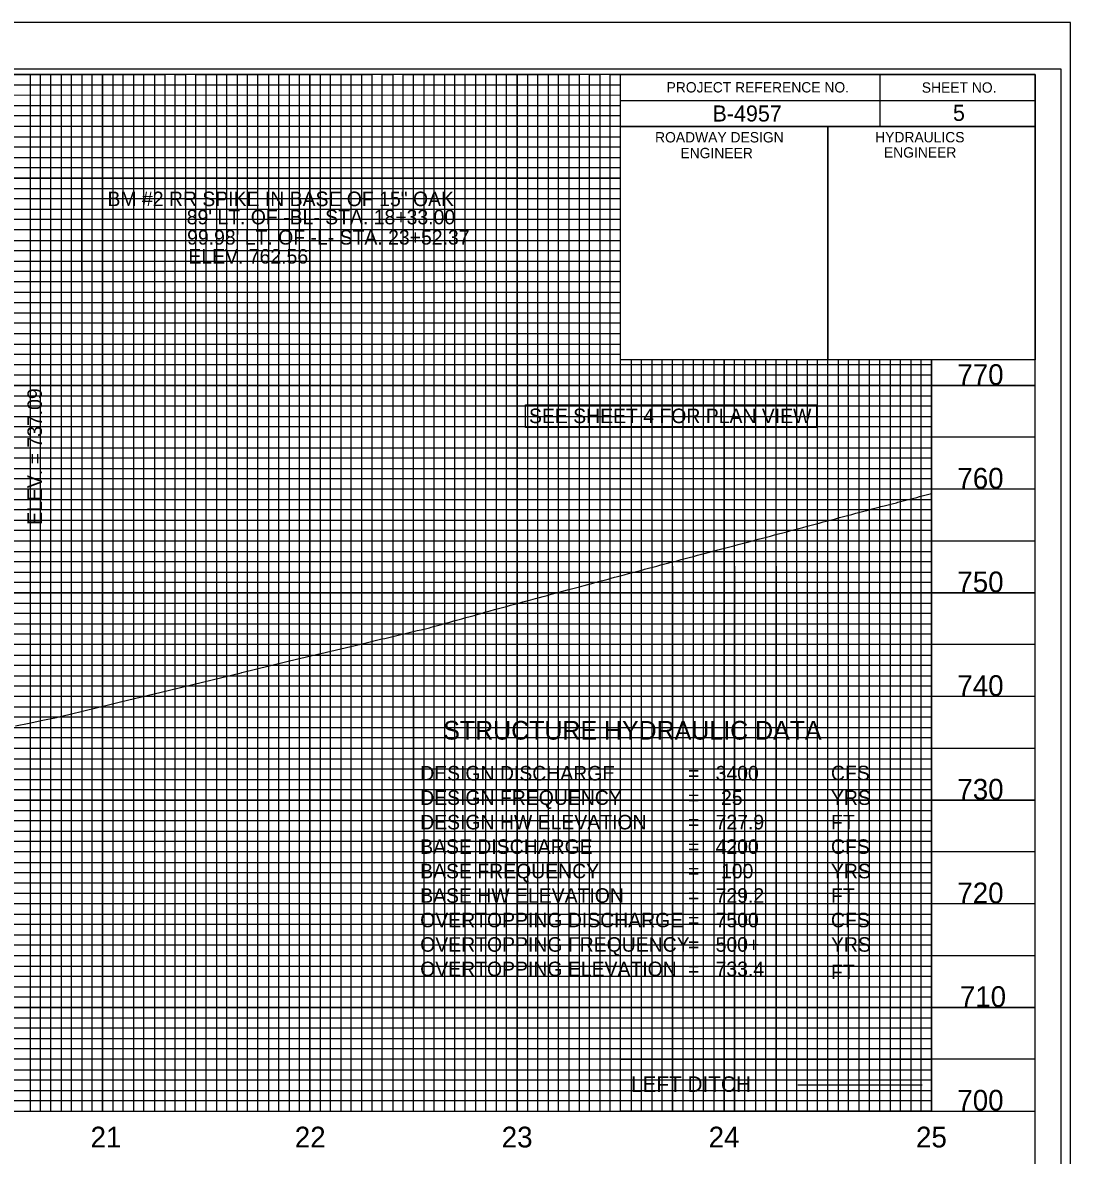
# Model space of a CAD drawing. Extents: x 573926 to 575610, y -51565 to -50465.
# Drawn here: x 575104 to 575610, y -51011 to -50465 of the extents above; entities that cross this region are included whole.
import ezdxf

# ---------------------------------------------------------------- set-up
doc = ezdxf.new("R2010")
doc.units = 0
for name, color, linetype in [('Exist Vertical Profile Ground Line', 7, 'Continuous'), ('Exist Vertical Profile Horizontal Axis Label Major', 7, 'Continuous'), ('Exist Vertical Profile Vertical Axis Label', 7, 'Continuous'), ('Prop Dimension Text', 7, 'Continuous'), ('Prop Grid Mask', 7, 'Continuous'), ('Prop PFL Ditch Label CELL', 7, 'Continuous'), ('Prop PFL Structure Hydraulic Data Label CELL', 7, 'Continuous'), ('Prop PFL Text', 7, 'Continuous'), ('Sheet Cutting Line CELL', 7, 'Continuous'), ('Sheet Data Field CELL', 7, 'Continuous'), ('Sheet DOT Grid CELL', 7, 'Continuous'), ('Sheet Layout Profile Border Port 1', 7, 'Continuous'), ('Sheet Plot Border Inside CELL', 7, 'Continuous'), ('Sheet Plot Border Outside CELL', 7, 'Continuous'), ('Sheet Profile CELL', 7, 'Continuous'), ('Sheet Profile Grid Major CELL', 7, 'Continuous'), ('Sheet Profile Grid Middle CELL', 7, 'Continuous'), ('Sheet Profile Grid Minor CELL', 7, 'Continuous')]:
    doc.layers.add(name, color=color, linetype=linetype)

msp = doc.modelspace()

# ---------------------------------------------------------------- linework, layer by layer
at = {"layer": 'Exist Vertical Profile Ground Line'}
for points in [[(575382.79, -50734.35), (575384.75, -50733.83), (575386.71, -50733.3), (575388.67, -50732.78), (575389.37, -50732.59), (575389.89, -50732.46), (575390.63, -50732.26), (575392.59, -50731.74), (575394.55, -50731.21), (575396.5, -50730.69), (575398.46, -50730.17), (575400.42, -50729.65), (575402.38, -50729.13), (575404.03, -50728.7), (575404.34, -50728.61), (575406.3, -50728.09), (575408.26, -50727.57), (575410.22, -50727.05), (575412.18, -50726.53), (575414.14, -50726.02), (575416.1, -50725.5), (575417.17, -50725.22), (575417.48, -50725.14), (575418.06, -50724.99), (575420.02, -50724.47), (575421.98, -50723.94), (575423.94, -50723.42), (575425.9, -50722.9), (575427.86, -50722.38), (575429.81, -50721.86), (575431.77, -50721.34), (575433.73, -50720.83), (575435.69, -50720.31), (575437.2, -50719.91), (575437.65, -50719.8), (575439.61, -50719.28), (575441.57, -50718.76), (575443.53, -50718.24), (575445.49, -50717.72), (575447.45, -50717.21), (575449.41, -50716.69), (575451.37, -50716.17), (575453.33, -50715.65), (575455.29, -50715.14), (575457.53, -50714.55), (575458.04, -50714.42), (575459.21, -50714.11), (575461.17, -50713.59), (575463.12, -50713.08), (575465.08, -50712.56), (575467.04, -50712.04), (575469, -50711.52), (575470.96, -50711), (575471.63, -50710.82), (575472.92, -50710.48), (575474.88, -50709.96), (575476.84, -50709.43), (575478.8, -50708.91), (575480.76, -50708.39), (575482.72, -50707.86), (575484.68, -50707.34), (575486.64, -50706.82), (575488.6, -50706.29), (575490.56, -50705.77), (575491.89, -50705.42), (575492.52, -50705.25), (575494.48, -50704.73), (575496.43, -50704.2), (575498.39, -50703.68), (575500.35, -50703.16), (575502.31, -50702.63), (575504.27, -50702.11), (575506.23, -50701.59), (575508.19, -50701.07), (575510.15, -50700.54), (575512.15, -50700.01), (575514.07, -50699.51), (575516.03, -50698.99), (575517.99, -50698.48), (575518.37, -50698.38), (575519.95, -50697.97), (575521.91, -50697.47), (575523.87, -50696.97), (575525.83, -50696.47), (575526.5, -50696.3), (575527.79, -50695.96), (575529.74, -50695.45), (575531.7, -50694.94), (575533.66, -50694.43), (575535.62, -50693.92), (575537.01, -50693.57), (575537.58, -50693.41), (575539.54, -50692.87), (575541.5, -50692.33), (575542.78, -50691.98)], [(575100.76, -50804.12), (575107.36, -50802.75), (575113.97, -50801.38), (575120.57, -50800.01), (575121.06, -50799.91), (575127.18, -50798.43), (575133.78, -50796.84), (575140.39, -50795.25), (575146.99, -50793.66), (575151.41, -50792.6), (575174.39, -50787.01), (575181.62, -50785.26), (575209.6, -50778.47), (575210.05, -50778.35), (575237.62, -50771.66), (575238.53, -50771.43), (575267.42, -50764.65), (575269.96, -50764.02), (575276.98, -50762.37), (575278.94, -50761.91), (575280.9, -50761.45), (575282.86, -50760.98), (575284.82, -50760.52), (575286.78, -50760.06), (575288.74, -50759.59), (575290.7, -50759.13), (575292.66, -50758.67), (575294.61, -50758.2), (575296.57, -50757.74), (575297.22, -50757.58), (575297.79, -50757.43), (575298.69, -50757.33), (575300.49, -50756.85), (575301.43, -50756.59), (575302.45, -50756.27), (575303.15, -50756.05), (575304.41, -50755.7), (575306.37, -50755.16), (575308.33, -50754.62), (575310.29, -50754.08), (575312.25, -50753.54), (575314.21, -50753), (575316.17, -50752.46), (575318.13, -50751.92), (575320.09, -50751.38), (575322.05, -50750.84), (575324.01, -50750.3), (575325.37, -50749.93), (575325.97, -50749.75), (575327.3, -50749.35), (575327.92, -50749.16), (575329.2, -50748.79), (575329.88, -50748.61), (575331.84, -50748.07), (575333.8, -50747.54), (575335.76, -50747.01), (575337.72, -50746.47), (575339.68, -50745.94), (575341.64, -50745.41), (575343.6, -50744.89), (575345.56, -50744.36), (575347.52, -50743.83), (575349.48, -50743.31), (575351.7, -50742.71), (575353.62, -50742.19), (575355.36, -50741.73), (575357.32, -50741.2), (575359.28, -50740.67), (575361.23, -50740.15), (575363.19, -50739.62), (575365.38, -50739.04), (575367.11, -50738.57), (575369.07, -50738.04), (575371.03, -50737.51), (575372.99, -50736.99), (575375.18, -50736.4), (575376.91, -50735.94), (575378.87, -50735.41), (575380.83, -50734.88), (575382.79, -50734.35)]]:
    msp.add_lwpolyline(points, dxfattribs=at)
at = {"layer": 'Prop Grid Mask'}
for points in [[(575132.78, -50539.95), (575342.78, -50539.95), (575342.78, -50584.95), (575132.78, -50584.95)], [(575346.87, -50649.35), (575487.28, -50649.35), (575487.28, -50660.17), (575346.87, -50660.17)], [(575292.78, -50939.95), (575517.78, -50939.95), (575517.78, -50789.95), (575292.78, -50789.95)], [(575392.78, -50964.95), (575542.78, -50964.95), (575542.78, -50989.95), (575392.78, -50989.95)]]:
    msp.add_lwpolyline(points, close=True, dxfattribs=at)
at = {"layer": 'Prop PFL Ditch Label CELL'}
msp.add_line((575478.33, -50977.25), (575538.33, -50977.25), dxfattribs=at)
at = {"layer": 'Sheet Cutting Line CELL'}
msp.add_line((575609.78, -50464.95), (573925.78, -50464.95), dxfattribs=at)
at = {"layer": 'Sheet DOT Grid CELL'}
for p, q in [((575142.78, -50989.95), (575142.78, -50489.95)), ((575192.78, -50989.95), (575192.78, -50489.95)), ((575242.78, -50989.95), (575242.78, -50489.95)), ((575292.78, -50989.95), (575292.78, -50489.95)), ((575342.78, -50989.95), (575342.78, -50489.95)), ((575392.73, -50539.95), (574092.78, -50539.95)), ((575392.73, -50589.95), (574092.78, -50589.95)), ((575392.78, -50989.95), (575392.78, -50627.5)), ((575442.78, -50989.95), (575442.78, -50627.5)), ((575492.78, -50989.95), (575492.78, -50627.5)), ((575542.78, -50989.95), (575542.78, -50627.5)), ((575592.78, -50639.95), (574092.78, -50639.95)), ((575592.78, -50689.95), (574092.78, -50689.95)), ((575592.78, -50739.95), (574092.78, -50739.95)), ((575592.78, -50789.95), (574092.78, -50789.95)), ((575592.78, -50839.95), (574092.78, -50839.95)), ((575592.78, -50889.95), (574092.78, -50889.95)), ((575592.78, -50939.95), (574092.78, -50939.95))]:
    msp.add_line(p, q, dxfattribs=at)
at = {"layer": 'Sheet Layout Profile Border Port 1'}
msp.add_lwpolyline([(574142.78, -50489.95), (574142.78, -50989.95), (575542.78, -50989.95), (575542.78, -50627.5), (575392.73, -50627.5), (575392.73, -50489.95)], close=True, dxfattribs=at)
at = {"layer": 'Sheet Plot Border Inside CELL'}
msp.add_lwpolyline([(573938.78, -51542.5), (575605.28, -51542.5), (575605.28, -50487.4), (573938.78, -50487.4)], close=True, dxfattribs=at)
at = {"layer": 'Sheet Plot Border Outside CELL'}
msp.add_lwpolyline([(573925.78, -51564.95), (575609.78, -51564.95), (575609.78, -50464.95), (573925.78, -50464.95)], close=True, dxfattribs=at)
at = {"layer": 'Sheet Profile CELL'}
for p, q in [((575517.78, -50490), (575517.78, -50515)), ((575392.73, -50502.5), (575592.78, -50502.5)), ((575492.78, -50515), (575492.78, -50627.45)), ((574092.78, -50989.95), (575592.78, -50989.95))]:
    msp.add_line(p, q, dxfattribs=at)
for points in [[(575592.78, -50489.95), (574092.78, -50489.95), (574092.78, -51539.95), (575592.78, -51539.95)], [(575392.73, -50489.95), (575592.78, -50489.95), (575592.78, -50515), (575392.73, -50515)], [(575392.73, -50515), (575492.78, -50515), (575492.78, -50627.5), (575392.73, -50627.5)], [(575492.78, -50515), (575592.78, -50515), (575592.78, -50627.5), (575492.78, -50627.5)]]:
    msp.add_lwpolyline(points, close=True, dxfattribs=at)
at = {"layer": 'Sheet Profile Grid Major CELL'}
for points in [[(575092.78, -50489.95), (575142.78, -50489.95), (575142.78, -50989.95), (575192.78, -50989.95), (575192.78, -50489.95), (575242.78, -50489.95), (575242.78, -50989.95), (575292.78, -50989.95), (575292.78, -50489.95), (575342.78, -50489.95), (575342.78, -50989.95), (575392.78, -50989.95), (575392.78, -50489.95), (575419.08, -50489.95)], [(574092.78, -50539.95), (575392.78, -50539.95)], [(575392.78, -50589.95), (574092.78, -50589.95), (574092.78, -50639.95), (575592.78, -50639.95)], [(575442.78, -50627.5), (575442.78, -50989.95), (575492.78, -50989.95), (575492.78, -50989.95), (575492.78, -50627.5)], [(575542.78, -50627.5), (575542.78, -50989.95), (575592.78, -50989.95), (575592.78, -50639.95)], [(575592.78, -50689.95), (574092.78, -50689.95), (574092.78, -50739.95), (575592.78, -50739.95)], [(575592.78, -50789.95), (574092.78, -50789.95), (574092.78, -50839.95), (575592.78, -50839.95)], [(575592.78, -50889.95), (574092.78, -50889.95), (574092.78, -50889.95), (574092.78, -50939.95), (575592.78, -50939.95)]]:
    msp.add_lwpolyline(points, dxfattribs=at)
at = {"layer": 'Sheet Profile Grid Middle CELL'}
msp.add_line((574092.78, -50514.95), (575392.73, -50514.95), dxfattribs=at)
for points in [[(575067.78, -50989.95), (575117.78, -50989.95), (575117.78, -50489.95), (575167.78, -50489.95), (575167.78, -50989.95), (575217.78, -50989.95), (575217.78, -50489.95), (575267.78, -50489.95), (575267.78, -50989.95), (575317.78, -50989.95), (575317.78, -50489.95), (575367.78, -50489.95), (575367.78, -50989.95), (575417.78, -50989.95), (575417.78, -50627.5)], [(575392.78, -50564.95), (574092.78, -50564.95), (574092.78, -50614.95), (575392.78, -50614.95)], [(575417.78, -50727.15), (575417.78, -50989.95), (575467.78, -50989.95), (575467.78, -50627.5)], [(575467.78, -50727.15), (575467.78, -50989.95), (575517.78, -50989.95), (575517.78, -50627.5)], [(575592.78, -50664.95), (574092.78, -50664.95), (574092.78, -50714.95), (575417.78, -50714.95)], [(575417.78, -50714.95), (575592.78, -50714.95)], [(575592.78, -50764.95), (574092.78, -50764.95), (574092.78, -50814.95), (575592.78, -50814.95)], [(575592.78, -50864.95), (574092.78, -50864.95), (574092.78, -50914.95), (575592.78, -50914.95)], [(575592.78, -50964.95), (574092.78, -50964.95)]]:
    msp.add_lwpolyline(points, dxfattribs=at)
at = {"layer": 'Sheet Profile Grid Minor CELL'}
for p, q in [((574142.78, -50494.95), (575392.78, -50494.95)), ((575392.78, -50499.95), (574142.78, -50500.3)), ((574142.78, -50504.95), (575392.78, -50504.95)), ((575392.73, -50624.95), (574142.78, -50624.95)), ((575542.78, -50629.95), (574142.78, -50629.95)), ((575542.78, -50634.95), (574142.78, -50634.95)), ((574142.78, -50644.95), (575542.78, -50644.95)), ((575542.78, -50649.95), (574142.78, -50649.95)), ((574142.78, -50654.95), (575542.78, -50654.95)), ((575542.78, -50674.95), (574142.78, -50674.95)), ((574142.78, -50679.95), (575542.78, -50679.95)), ((575542.78, -50699.95), (574142.78, -50699.95)), ((574142.78, -50704.95), (575542.78, -50704.95)), ((575542.78, -50724.95), (574142.78, -50724.95)), ((574142.78, -50729.95), (575542.78, -50729.95)), ((575542.78, -50734.95), (574142.78, -50734.95)), ((574142.78, -50744.95), (575542.78, -50744.95)), ((575542.78, -50749.95), (574142.78, -50749.95)), ((574142.78, -50754.95), (575542.78, -50754.95)), ((575542.78, -50759.95), (574142.78, -50759.95)), ((574142.78, -50769.95), (575542.78, -50769.95)), ((575542.78, -50774.95), (574142.78, -50774.95)), ((574142.78, -50779.95), (575542.78, -50779.95)), ((575542.78, -50784.95), (574142.78, -50784.95)), ((574142.78, -50794.95), (575542.78, -50794.95)), ((575542.78, -50799.95), (574142.78, -50799.95)), ((574142.78, -50804.95), (575542.78, -50804.95)), ((575542.78, -50809.95), (574142.78, -50809.95)), ((574142.78, -50819.95), (575542.78, -50819.95)), ((575542.78, -50824.95), (574142.78, -50824.95)), ((574142.78, -50829.95), (575542.78, -50829.95)), ((575542.78, -50834.95), (574142.78, -50834.95)), ((574142.78, -50844.95), (575542.78, -50844.95)), ((575542.78, -50849.95), (574142.78, -50849.95)), ((574142.78, -50854.95), (575542.78, -50854.95)), ((575542.78, -50859.95), (574142.78, -50859.95)), ((574142.78, -50869.95), (575542.78, -50869.95)), ((575542.78, -50874.95), (574142.78, -50874.95)), ((575542.78, -50879.95), (574142.78, -50879.95)), ((575542.78, -50884.95), (574142.78, -50884.95)), ((574142.78, -50894.95), (575542.78, -50894.95)), ((575542.78, -50899.95), (574142.78, -50899.95)), ((574142.78, -50904.95), (575542.78, -50904.95)), ((575542.78, -50909.95), (574142.78, -50909.95)), ((574142.78, -50919.95), (575542.78, -50919.95)), ((575542.78, -50924.95), (574142.78, -50924.95)), ((574142.78, -50929.95), (575542.78, -50929.95)), ((575542.78, -50934.95), (574142.78, -50934.95)), ((574142.78, -50944.95), (575542.78, -50944.95)), ((575542.78, -50949.95), (574142.78, -50949.95)), ((574142.78, -50954.95), (575542.78, -50954.95)), ((575542.78, -50959.95), (574142.78, -50959.95)), ((574142.78, -50969.95), (575542.78, -50969.95)), ((575542.78, -50974.95), (574142.78, -50974.95)), ((574142.78, -50979.95), (575542.78, -50979.95))]:
    msp.add_line(p, q, dxfattribs=at)
for points in [[(575102.78, -50489.95), (575107.78, -50489.95), (575107.78, -50989.95), (575112.78, -50989.95), (575112.78, -50489.95), (575122.78, -50489.95), (575122.78, -50989.95), (575127.78, -50989.95), (575127.78, -50489.95), (575132.78, -50489.95), (575132.78, -50989.95), (575137.78, -50989.95), (575137.78, -50489.95), (575147.78, -50489.95), (575147.78, -50989.95), (575152.78, -50989.95), (575152.78, -50489.95), (575157.78, -50489.95), (575157.78, -50989.95), (575162.78, -50989.95), (575162.78, -50489.95), (575172.78, -50489.95), (575172.78, -50989.95), (575177.78, -50989.95), (575177.78, -50489.95), (575182.78, -50489.95), (575182.78, -50989.95), (575187.78, -50989.95), (575187.78, -50489.95), (575197.78, -50489.95), (575197.78, -50989.95), (575202.78, -50989.95), (575202.78, -50489.95), (575207.78, -50489.95), (575207.78, -50989.95), (575212.78, -50989.95), (575212.78, -50489.95), (575222.78, -50489.95), (575222.78, -50989.95), (575227.78, -50989.95), (575227.78, -50489.95), (575232.78, -50489.95), (575232.78, -50989.95), (575237.78, -50989.95), (575237.78, -50489.95), (575247.78, -50489.95), (575247.78, -50989.95), (575252.78, -50989.95), (575252.78, -50489.95), (575257.78, -50489.95), (575257.78, -50989.95), (575262.78, -50989.95), (575262.78, -50489.95), (575272.78, -50489.95), (575272.78, -50989.95), (575277.78, -50989.95), (575277.78, -50489.95), (575282.78, -50489.95), (575282.78, -50989.95)], [(575282.78, -50989.95), (575287.78, -50989.95), (575287.78, -50489.95), (575297.78, -50489.95), (575297.78, -50989.95), (575302.78, -50989.95), (575302.78, -50489.95), (575307.78, -50489.95), (575307.78, -50989.95), (575312.78, -50989.95), (575312.78, -50489.95), (575322.78, -50489.95), (575322.78, -50989.95), (575327.78, -50989.95), (575327.78, -50489.95), (575332.78, -50489.95), (575332.78, -50989.95), (575337.78, -50989.95), (575337.78, -50489.95), (575347.78, -50489.95), (575347.78, -50989.95), (575352.78, -50989.95), (575352.78, -50489.95), (575357.78, -50489.95), (575357.78, -50989.95), (575362.78, -50989.95), (575362.78, -50489.95), (575372.78, -50489.95), (575372.78, -50989.95), (575377.78, -50989.95), (575377.78, -50489.95), (575382.78, -50489.95), (575382.78, -50989.95), (575387.78, -50989.95), (575387.78, -50489.95), (575397.78, -50489.95)], [(575392.78, -50509.95), (574142.78, -50509.95), (574142.78, -50519.95), (575392.78, -50519.95)], [(575392.73, -50524.95), (574142.78, -50524.95), (574142.78, -50529.95), (575392.78, -50529.95)], [(575392.78, -50534.95), (574142.78, -50534.95), (574142.78, -50544.95), (575392.78, -50544.95)], [(575392.78, -50549.95), (574142.78, -50549.95), (574142.78, -50554.95), (575392.78, -50554.95)], [(575392.78, -50559.95), (574142.78, -50559.95), (574142.78, -50569.95), (575392.78, -50569.95)], [(575392.78, -50574.95), (574142.78, -50574.95), (574142.78, -50579.95), (575392.78, -50579.95)], [(575392.78, -50584.95), (574142.78, -50584.95), (574142.78, -50594.95), (575392.78, -50594.95)], [(575392.78, -50600.05), (574142.88, -50600.05), (574142.88, -50604.95), (575392.78, -50604.95)], [(575392.78, -50609.95), (574142.78, -50609.95), (574142.78, -50619.95), (575392.78, -50619.95)], [(575397.78, -50627.5), (575397.78, -50989.95), (575402.78, -50989.95), (575402.78, -50627.5)], [(575407.78, -50627.5), (575407.78, -50989.95), (575412.78, -50989.95), (575412.78, -50627.5)], [(575422.78, -50627.5), (575422.78, -50989.95), (575422.78, -50989.95), (575427.78, -50989.95), (575432.78, -50989.95), (575432.78, -50627.5)], [(575427.78, -50627.5), (575427.78, -50989.95)], [(575437.78, -50627.5), (575437.68, -50989.9), (575442.68, -50989.9), (575447.78, -50989.95), (575447.78, -50627.5)], [(575447.78, -50727.15), (575447.78, -50989.95), (575452.78, -50989.95), (575452.78, -50627.5)], [(575457.78, -50627.5), (575457.78, -50989.95), (575462.78, -50989.95), (575462.78, -50627.5)], [(575472.78, -50627.5), (575472.78, -50989.95), (575477.78, -50989.95), (575477.78, -50627.5)], [(575482.78, -50627.5), (575482.78, -50989.95), (575487.78, -50989.95), (575487.78, -50627.5)], [(575497.78, -50627.5), (575497.78, -50989.95), (575502.78, -50989.95), (575502.78, -50627.5)], [(575507.78, -50627.5), (575507.78, -50989.95), (575512.78, -50989.95), (575512.78, -50627.5)], [(575522.78, -50627.5), (575522.78, -50989.95), (575527.78, -50989.95), (575527.78, -50627.5)], [(575532.78, -50627.5), (575532.78, -50989.95), (575537.78, -50989.95), (575537.78, -50627.5)], [(575542.78, -50659.95), (574142.78, -50659.95), (574142.78, -50669.95), (575542.78, -50669.95)], [(575542.78, -50684.95), (574142.78, -50684.95), (574142.78, -50694.95), (575542.78, -50694.95)], [(575542.78, -50709.95), (574142.78, -50709.95), (574142.78, -50719.95), (575542.78, -50719.95)], [(575542.78, -50984.95), (574142.78, -50984.95)]]:
    msp.add_lwpolyline(points, dxfattribs=at)

# ---------------------------------------------------------------- texts
at = {"layer": 'Exist Vertical Profile Horizontal Axis Label Major'}
for s, p in [('21', (575137, -51007.45)), ('22', (575235.55, -51007.45)), ('23', (575335.39, -51007.45)), ('24', (575435.23, -51007.45)), ('25', (575535.32, -51007.45))]:
    msp.add_text(s, height=10, dxfattribs=at).set_placement(p)
at = {"layer": 'Exist Vertical Profile Vertical Axis Label'}
for s, p in [('770', (575555.25, -50639.7)), ('760', (575555.25, -50689.7)), ('750', (575555.25, -50739.7)), ('740', (575555.25, -50789.7)), ('730', (575555.25, -50839.7)), ('720', (575555.25, -50889.7)), ('710', (575556.45, -50939.7)), ('700', (575555.25, -50989.7))]:
    msp.add_text(s, height=10, dxfattribs=at).set_placement(p)
at = {"layer": 'Prop Dimension Text'}
for s, p in [('BM #2 RR SPIKE IN BASE OF 15" OAK', (575145.16, -50553.44)), ("89' LT. OF -BL- STA. 18+33.00", (575183.4, -50562.22)), ("99.98' LT. OF -L- STA. 23+52.37", (575183.59, -50571.99)), ("ELEV. 762.56'", (575184.21, -50581.16))]:
    msp.add_text(s, height=7, dxfattribs=at).set_placement(p)
msp.add_text('ELEV. = 737.09', height=7, rotation=90, dxfattribs=at).set_placement((575113.53, -50707.15))
at = {"layer": 'Prop PFL Ditch Label CELL'}
msp.add_text('LEFT DITCH', height=7.485, dxfattribs=at).set_placement((575397.78, -50980.65))
at = {"layer": 'Prop PFL Structure Hydraulic Data Label CELL'}
for s, height, p in [('STRUCTURE HYDRAULIC DATA', 9, (575307.2, -50810.75)), ('DESIGN DISCHARGE', 6.9999, (575296.05, -50830.45)), ('=   3400', 7, (575425.33, -50830.45)), ('CFS', 7, (575494.26, -50830.35)), ('DESIGN FREQUENCY', 6.9999, (575296.05, -50842.25)), ('=    25', 7, (575425.33, -50842.25)), ('YRS', 7, (575494.26, -50842.25)), ('DESIGN HW ELEVATION', 6.9999, (575296.05, -50854.05)), ('=   727.9', 7, (575425.33, -50854.05)), ('FT', 7, (575494.26, -50854.05)), ('BASE DISCHARGE', 6.9999, (575296.05, -50865.85)), ('=   4200', 7, (575425.33, -50865.85)), ('CFS', 7, (575494.26, -50865.85)), ('BASE FREQUENCY', 6.9999, (575296.05, -50877.65)), ('=    100', 7, (575425.33, -50877.65)), ('YRS', 7, (575494.26, -50877.65)), ('BASE HW ELEVATION', 6.9999, (575296.05, -50889.45)), ('=   729.2', 7, (575425.33, -50889.45)), ('FT', 7, (575494.26, -50889.45)), ('OVERTOPPING DISCHARGE', 6.9999, (575296.05, -50901.25)), ('=   7500', 7, (575425.33, -50901.25)), ('CFS', 7, (575494.26, -50901.25)), ('OVERTOPPING FREQUENCY', 6.9999, (575296.05, -50913.05)), ('=   500+', 7, (575425.33, -50913.05)), ('YRS', 7, (575494.26, -50913.05)), ('OVERTOPPING ELEVATION', 6.9999, (575296.05, -50924.85)), ('=   733.4', 7, (575425.33, -50924.85)), ('FT', 7, (575494.26, -50926.24))]:
    msp.add_text(s, height=height, dxfattribs=at).set_placement(p)
at = {"layer": 'Prop PFL Text'}
msp.add_text('SEE SHEET 4 FOR PLAN VIEW', height=7, dxfattribs=at).set_placement((575348.55, -50658.1))
at = {"layer": 'Sheet Data Field CELL'}
for s, p in [('B-4957', (575437.11, -50512.63)), ('5', (575553.13, -50512.33))]:
    msp.add_text(s, height=7.75, dxfattribs=at).set_placement(p)
at = {"layer": 'Sheet Profile CELL'}
for s, height, p in [('PROJECT REFERENCE NO.', 5.0001, (575414.94, -50498.63)), ('SHEET NO.', 5, (575538.09, -50498.73)), ('ROADWAY DESIGN', 5.0001, (575409.39, -50522.73)), ('HYDRAULICS', 5, (575515.59, -50522.68)), ('ENGINEER', 5, (575421.64, -50530.33)), ('ENGINEER', 5, (575519.84, -50530.03))]:
    msp.add_text(s, height=height, dxfattribs=at).set_placement(p)

doc.saveas('drawing.dxf')
